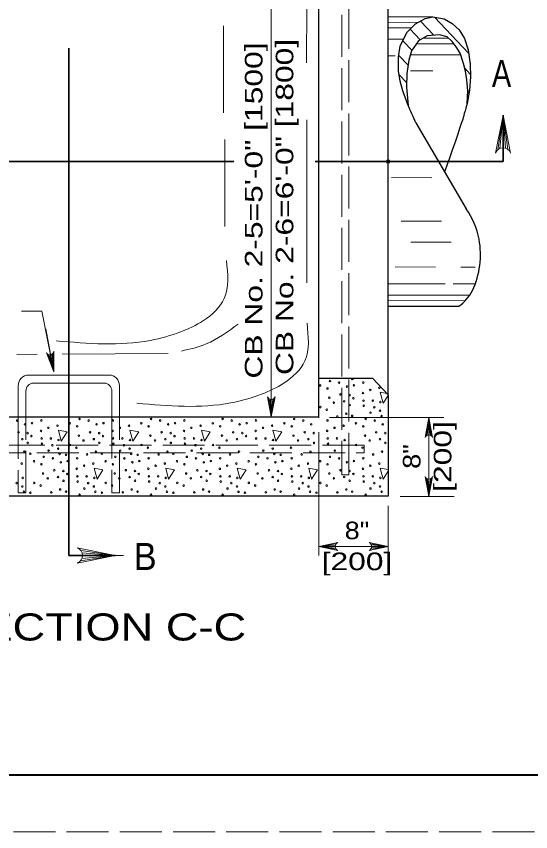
# Model space of a CAD drawing. Extents: x 1329.9 to 1363.9, y 715.5 to 737.5.
# Drawn here: x 1350.19 to 1354.75, y 715.5 to 722.72 of the extents above; entities that cross this region are included whole.
import ezdxf
from ezdxf.enums import TextEntityAlignment as Align

# ---------------------------------------------------------------- set-up
doc = ezdxf.new("R2010")
doc.units = 0
doc.header["$LTSCALE"] = 0.062
doc.header["$PDMODE"] = 32
doc.header["$PDSIZE"] = 0.031
doc.linetypes.add('DASH_DOUBLE_DOT', pattern=[9.2, 5, -1.2, 0.3, -1.2, 0.3, -1.2])
doc.linetypes.add('LONG_DASHED', pattern=[7.5, 6, -1.5])
doc.layers.add('1', color=7, linetype='Continuous', lineweight=13)

msp = doc.modelspace()

# ---------------------------------------------------------------- linework, layer by layer
at = {"layer": '1'}
for p, q in [((1352.44608, 719.17433), (1352.44608, 723.75258)), ((1352.75967, 722.31133), (1352.76208, 722.82492)), ((1353.48483, 722.72117), (1353.88033, 722.72058)), ((1353.89325, 722.71792), (1354.19717, 722.39533)), ((1352.02267, 721.87), (1352.02133, 722.64067)), ((1353.48467, 722.6715), (1353.74925, 722.671)), ((1353.76842, 722.68158), (1353.88667, 722.556)), ((1353.48467, 722.62183), (1353.68817, 722.6215)), ((1353.67675, 722.61), (1353.76625, 722.515)), ((1353.48458, 722.52233), (1353.61992, 722.52217)), ((1353.6135, 722.50825), (1353.6925, 722.42433)), ((1353.795, 722.53158), (1354.01642, 722.53125)), ((1353.73333, 722.48192), (1354.06483, 722.48133)), ((1353.48425, 722.37333), (1353.5445, 722.37308)), ((1353.57692, 722.37808), (1353.65975, 722.29008)), ((1353.67925, 722.38258), (1354.12558, 722.38192)), ((1353.5805, 722.2055), (1353.64717, 722.13458)), ((1353.68183, 722.24175), (1353.87867, 722.24142)), ((1354.162, 722.26358), (1354.21125, 722.21142)), ((1354.18892, 722.06625), (1354.2015, 722.05308)), ((1354.18908, 722.06125), (1354.20067, 722.04875)), ((1354.18533, 721.99475), (1354.18992, 721.99)), ((1353.65158, 721.96108), (1353.65992, 721.952)), ((1353.65917, 721.93992), (1353.66133, 721.93775)), ((1354.45492, 721.54117), (1354.502, 721.84933)), ((1354.47467, 721.55283), (1354.502, 721.84933)), ((1354.502, 721.55817), (1354.502, 721.84933)), ((1354.52358, 721.555), (1354.502, 721.84933)), ((1354.54467, 721.54475), (1354.502, 721.84933)), ((1352.76317, 720.36333), (1352.76058, 721.80692)), ((1352.03592, 720.86092), (1352.03458, 721.63167)), ((1353.51117, 721.29467), (1353.86883, 721.29425)), ((1353.59808, 720.90783), (1353.95575, 720.90742)), ((1353.68517, 720.72367), (1354.04283, 720.72317)), ((1353.54592, 720.50267), (1353.90358, 720.50217)), ((1354.12883, 720.50183), (1354.25567, 720.50175)), ((1353.4815, 720.35375), (1353.9885, 720.35292)), ((1354.0585, 720.35292), (1354.25542, 720.35258)), ((1353.48125, 720.25433), (1354.20592, 720.25317)), ((1353.48125, 720.20467), (1354.16575, 720.2035)), ((1350.23242, 720.11083), (1350.41208, 720.11083)), ((1350.51892, 719.57433), (1350.41208, 720.11083)), ((1350.44733, 719.95367), (1350.51892, 719.57433)), ((1350.18917, 719.72842), (1350.37, 719.72883)), ((1350.46817, 719.72808), (1350.51892, 719.57433)), ((1350.4795, 719.72492), (1350.51892, 719.57433)), ((1350.49033, 719.72542), (1350.51892, 719.57433)), ((1350.50333, 719.73108), (1350.51892, 719.57433)), ((1350.51183, 719.73925), (1350.51892, 719.57433)), ((1350.59333, 719.72933), (1351.53267, 719.73492)), ((1351.01, 719.54458), (1350.29225, 719.54458)), ((1350.33708, 719.47333), (1350.96517, 719.47333)), ((1350.2025, 719.44958), (1350.2025, 719.17383)), ((1350.26983, 719.17208), (1350.26983, 719.40208)), ((1351.03242, 719.40208), (1351.03242, 719.17608)), ((1351.09967, 719.17383), (1351.09967, 719.44958)), ((1353.4725, 719.38092), (1353.41317, 719.39242)), ((1352.42475, 719.3355), (1352.44608, 719.17433)), ((1352.43533, 719.33008), (1352.44608, 719.17433)), ((1352.46958, 719.33742), (1352.44608, 719.17433)), ((1352.45975, 719.33125), (1352.44608, 719.17433)), ((1352.44608, 719.32842), (1352.44608, 719.17433)), ((1352.86742, 719.17433), (1352.86742, 719.1655)), ((1353.97692, 719.16825), (1352.96392, 719.16825)), ((1353.82008, 719.00517), (1353.84367, 719.16825)), ((1353.83, 719.01133), (1353.84367, 719.16825)), ((1353.84367, 718.46808), (1353.84367, 719.16825)), ((1353.84367, 719.01417), (1353.84367, 719.16825)), ((1353.85442, 719.0125), (1353.84367, 719.16825)), ((1353.865, 719.00708), (1353.84367, 719.16825)), ((1352.86742, 719.03958), (1352.86742, 717.9465)), ((1353.48292, 718.70717), (1353.41317, 718.72083)), ((1353.41317, 718.72083), (1353.43875, 718.6235)), ((1353.43875, 718.6235), (1353.48292, 718.693)), ((1353.82233, 718.62933), (1353.84367, 718.46808)), ((1353.83292, 718.62383), (1353.84367, 718.46808)), ((1353.86717, 718.63125), (1353.84367, 718.46808)), ((1353.85733, 718.62508), (1353.84367, 718.46808)), ((1353.84367, 718.62217), (1353.84367, 718.46808)), ((1353.58833, 718.46808), (1354.0685, 718.46808)), ((1353.48158, 718.38683), (1353.48158, 717.9465)), ((1353.01975, 718.04775), (1352.86742, 718.02517)), ((1353.01458, 718.03658), (1352.86742, 718.02517)), ((1352.86742, 718.02517), (1353.48158, 718.02517)), ((1353.013, 718.02517), (1352.86742, 718.02517)), ((1353.01567, 718.01075), (1352.86742, 718.02517)), ((1353.0215, 718.00025), (1352.86742, 718.02517)), ((1353.3275, 718.05017), (1353.48158, 718.02517)), ((1353.32925, 718.00267), (1353.48158, 718.02517)), ((1353.33333, 718.03967), (1353.48158, 718.02517)), ((1353.33442, 718.01383), (1353.48158, 718.02517)), ((1353.336, 718.02517), (1353.48158, 718.02517)), ((1350.75433, 717.89917), (1351.06258, 717.94633)), ((1350.75792, 717.98892), (1351.06258, 717.94633)), ((1350.766, 717.91892), (1351.06258, 717.94633)), ((1350.76825, 717.96783), (1351.06258, 717.94633)), ((1350.77142, 717.94633), (1351.06258, 717.94633))]:
    msp.add_line(p, q, dxfattribs=at)
at = {"layer": '1', "lineweight": 25}
for p, q in [((1353.483, 719.36825), (1353.483, 723.55683)), ((1352.86742, 719.51625), (1352.86742, 723.41067)), ((1353.7295, 721.781), (1354.174, 721.01808)), ((1353.48108, 720.15492), (1354.10975, 720.154))]:
    msp.add_line(p, q, dxfattribs=at)
at = {"layer": '1', "lineweight": 35}
for p, q in [((1350.65133, 717.94633), (1350.65133, 722.44125)), ((1354.502, 721.84933), (1354.502, 721.43808)), ((1347.83075, 721.43808), (1352.11375, 721.43808)), ((1352.83567, 721.43808), (1354.502, 721.43808)), ((1351.06258, 717.94633), (1350.65133, 717.94633))]:
    msp.add_line(p, q, dxfattribs=at)
at = {"layer": '1', "linetype": 'LONG_DASHED'}
for p, q in [((1350.2025, 719.17383), (1350.2025, 718.49975)), ((1350.26983, 718.49975), (1350.26983, 719.17208)), ((1351.03242, 719.17608), (1351.03242, 718.49975)), ((1351.09967, 718.49975), (1351.09967, 719.17383)), ((1350.2025, 718.49975), (1350.26983, 718.49975)), ((1351.03242, 718.49975), (1351.09967, 718.49975))]:
    msp.add_line(p, q, dxfattribs=at)
at = {"layer": '1', "linetype": 'DASH_DOUBLE_DOT'}
msp.add_line((1351.13717, 717.94633), (1350.65133, 717.94633), dxfattribs=at)
at = {"layer": '1', "linetype": 'LONG_DASHED'}
for points in [[(1329.86333, 715.4975), (1363.86333, 715.4975), (1363.86333, 737.4975), (1329.86333, 737.4975)], [(1353.13433, 724.15242), (1353.07167, 724.15242), (1353.07167, 718.66), (1353.13433, 718.66)], [(1348.00833, 718.85575), (1353.27142, 718.85575), (1353.27142, 718.92208), (1348.00833, 718.92208)]]:
    msp.add_lwpolyline(points, close=True, dxfattribs=at)
at = {"layer": '1', "lineweight": 25}
for points in [[(1363.36333, 715.9975), (1331.86333, 715.9975), (1331.86333, 736.9975)], [(1353.66167, 721.933), (1353.6135, 722.06458), (1353.58942, 722.1505), (1353.57417, 722.24242), (1353.57483, 722.36567), (1353.59067, 722.45942), (1353.64733, 722.58125), (1353.7245, 722.65725), (1353.81025, 722.705), (1353.88033, 722.72058), (1353.98033, 722.70117), (1354.04933, 722.66058), (1354.11317, 722.60492), (1354.16142, 722.527), (1354.19308, 722.42867), (1354.20892, 722.30125), (1354.21208, 722.18692), (1354.2045, 722.06992), (1354.18292, 721.95225)], [(1353.66167, 721.933), (1353.6135, 722.06458), (1353.58942, 722.1505), (1353.57417, 722.24242), (1353.57483, 722.36567), (1353.59067, 722.45942), (1353.64733, 722.58125), (1353.7245, 722.65725), (1353.81025, 722.705), (1353.88033, 722.72058), (1353.98033, 722.70117), (1354.04933, 722.66058), (1354.11317, 722.60492), (1354.16142, 722.527), (1354.19308, 722.42867), (1354.20892, 722.30125), (1354.21208, 722.18692), (1354.2045, 722.06992), (1354.18292, 721.95225)], [(1354.18292, 721.95225), (1354.18917, 722.06317), (1354.18017, 722.16175), (1354.16917, 722.23717), (1354.151, 722.305), (1354.12017, 722.39783), (1354.08542, 722.454), (1354.04917, 722.5025), (1354.00517, 722.54117), (1353.93942, 722.56067), (1353.82992, 722.55117), (1353.75117, 722.50667), (1353.68908, 722.41983), (1353.66692, 722.33667), (1353.64858, 722.21875), (1353.6465, 722.09683), (1353.66167, 721.933)], [(1354.18292, 721.95225), (1354.18917, 722.06317), (1354.18017, 722.16175), (1354.16917, 722.23717), (1354.151, 722.305), (1354.12017, 722.39783), (1354.08542, 722.454), (1354.04917, 722.5025), (1354.00517, 722.54117), (1353.93942, 722.56067), (1353.82992, 722.55117), (1353.75117, 722.50667), (1353.68908, 722.41983), (1353.66692, 722.33667), (1353.64858, 722.21875), (1353.6465, 722.09683), (1353.66167, 721.933)], [(1348.49467, 719.17433), (1352.86742, 719.17433), (1352.86742, 719.51625), (1353.34492, 719.51625), (1353.483, 719.37008)], [(1353.483, 719.36825), (1353.483, 718.47142), (1347.83075, 718.47142), (1347.83075, 719.34)]]:
    msp.add_lwpolyline(points, dxfattribs=at)
at = {"layer": '1', "lineweight": 40}
msp.add_lwpolyline([(1331.86333, 736.9975), (1363.36333, 736.9975), (1363.36333, 715.9975), (1331.86333, 715.9975)], close=True, dxfattribs=at)
msp.add_lwpolyline([(1331.86333, 736.9975), (1363.36333, 736.9975), (1363.36333, 715.9975), (1331.86333, 715.9975)], close=True, dxfattribs=at)
at = {"layer": '1'}
for points in [[(1354.43475, 721.51283), (1354.502, 721.84933), (1354.56933, 721.51283)], [(1350.51892, 719.756), (1350.51892, 719.57433), (1350.453, 719.742)], [(1353.41317, 719.39242), (1353.43875, 719.29508), (1353.48292, 719.36467)], [(1352.47975, 719.35242), (1352.44608, 719.17433), (1352.41242, 719.35242)], [(1353.81, 718.99017), (1353.84367, 719.16825), (1353.87733, 718.99017)], [(1353.87733, 718.64617), (1353.84367, 718.46808), (1353.81, 718.64617)], [(1350.72608, 717.879), (1351.06258, 717.94633), (1350.72608, 718.01358)], [(1353.03567, 717.98958), (1352.86742, 718.02517), (1353.03567, 718.06083)], [(1353.31333, 718.06083), (1353.48158, 718.02517), (1353.31333, 717.98958)]]:
    msp.add_lwpolyline(points, dxfattribs=at)
for points in [[(1350.55833, 719.05658), (1350.584, 718.95933), (1350.63625, 719.0415)], [(1351.19275, 719.05658), (1351.21833, 718.95933), (1351.27058, 719.0415)], [(1351.82717, 719.05658), (1351.85283, 718.95933), (1351.905, 719.0415)], [(1352.4615, 719.05658), (1352.48717, 718.95933), (1352.53942, 719.0415)], [(1350.87558, 718.72083), (1350.90117, 718.6235), (1350.95342, 718.70567)], [(1351.50992, 718.72083), (1351.53558, 718.6235), (1351.58783, 718.70567)], [(1352.14433, 718.72083), (1352.16992, 718.6235), (1352.22225, 718.70567)], [(1352.77875, 718.72083), (1352.80442, 718.6235), (1352.85658, 718.70567)]]:
    msp.add_lwpolyline(points, close=True, dxfattribs=at)
for centre, start, end in [((1354.50209, 721.4857), 22.08782, 157.91395), ((1350.69893, 717.94637), 292.08605, 67.91218)]:
    msp.add_arc(centre, 0.07261, start, end, dxfattribs=at)
at = {"layer": '1', "lineweight": 25}
for centre, major_axis, start_param, end_param in [((1353.69011, 720.62359), (0, 0.64669), 4.9058986, 5.3686347), ((1353.62561, 720.61253), (0, 0.71577), 4.251341, 4.9027182), ((1353.8771, 720.50864), (0, -0.43184), 0.6070417, 1.0508543)]:
    msp.add_ellipse(centre, major_axis=major_axis, ratio=0.944544, start_param=start_param, end_param=end_param, dxfattribs=at)
at = {"layer": '1'}
for centre, major_axis, start_param, end_param in [((1350.48328, 719.76316), (0, -0.03844), 5.2952095, 7.6658226), ((1350.29224, 719.4496), (0, 0.09498), 6.2831853, 7.8539816), ((1351.00998, 719.4496), (0, 0.09498), 4.712389, 6.2831853), ((1350.3371, 719.4021), (0, 0.07124), 6.2831853, 7.8539816), ((1350.96513, 719.4021), (0, 0.07124), 4.712389, 6.2831853), ((1352.44606, 719.36685), (0, -0.03844), 5.0978942, 7.4685073), ((1353.84366, 718.97573), (0, 0.03844), 5.0978942, 7.4685073), ((1353.84365, 718.66064), (0, -0.03844), 5.0978942, 7.4685073), ((1353.04931, 718.0252), (0, 0.03844), 0.3855052, 2.7561184), ((1353.29968, 718.0252), (0, -0.03844), 0.3855052, 2.7561184)]:
    msp.add_ellipse(centre, major_axis=major_axis, ratio=0.944544, start_param=start_param, end_param=end_param, dxfattribs=at)
for centre in [(1352.87983, 719.45284), (1352.96637, 719.49185), (1353.04715, 719.47764), (1353.16451, 719.50932), (1353.17905, 719.45407), (1353.26216, 719.47848), (1352.94496, 719.42564), (1353.05973, 719.37308), (1353.11736, 719.44316), (1353.25904, 719.38573), (1353.32406, 719.41293), (1353.40548, 719.43196), (1352.9604, 719.34403), (1353.09314, 719.3123), (1353.14056, 719.36609), (1353.17424, 719.3395), (1353.26417, 719.31862), (1353.34643, 719.31862), (1353.41404, 719.30502), (1352.88157, 719.26058), (1352.93809, 719.23702), (1353.00153, 719.30049), (1353.14141, 719.27933), (1353.2667, 719.27239), (1353.36012, 719.25879), (1353.41061, 719.22885), (1353.03261, 719.17691), (1353.11144, 719.20226), (1353.16367, 719.18323), (1353.32666, 719.21071), (1353.42435, 719.18172), (1350.19236, 719.14181), (1350.26256, 719.10734), (1350.32426, 719.11825), (1350.40736, 719.14265), (1350.55068, 719.09614), (1350.65943, 719.11702), (1350.72456, 719.08982), (1350.74597, 719.15603), (1350.82675, 719.14181), (1350.89696, 719.10734), (1350.95866, 719.11825), (1351.04176, 719.14265), (1351.18508, 719.09614), (1351.29383, 719.11702), (1351.35896, 719.08982), (1351.38037, 719.15603), (1351.46115, 719.14181), (1351.53136, 719.10734), (1351.59305, 719.11825), (1351.67616, 719.14265), (1351.81948, 719.09614), (1351.92823, 719.11702), (1351.99336, 719.08982), (1352.01477, 719.15603), (1352.09555, 719.14181), (1352.16576, 719.10734), (1352.22745, 719.11825), (1352.31056, 719.14265), (1352.45388, 719.09614), (1352.56263, 719.11702), (1352.62776, 719.08982), (1352.64917, 719.15603), (1352.72995, 719.14181), (1352.80016, 719.10734), (1352.94496, 719.14265), (1353.08828, 719.09614), (1353.19703, 719.11702), (1353.26216, 719.08982), (1353.28357, 719.15603), (1353.36435, 719.14181), (1353.43456, 719.10734), (1350.20494, 719.03726), (1350.28577, 719.03026), (1350.40424, 719.04991), (1350.46927, 719.07711), (1350.83934, 719.03726), (1350.92017, 719.03026), (1351.03864, 719.04991), (1351.10367, 719.07711), (1351.47374, 719.03726), (1351.55457, 719.03026), (1351.67304, 719.04991), (1351.73807, 719.07711), (1352.10813, 719.03726), (1352.18897, 719.03026), (1352.30744, 719.04991), (1352.37247, 719.07711), (1352.74253, 719.03726), (1352.82337, 719.03026), (1352.94184, 719.04991), (1353.00687, 719.07711), (1353.37693, 719.03726), (1353.45776, 719.03026), (1350.23835, 718.97648), (1350.28662, 718.94351), (1350.31945, 719.00368), (1350.40937, 718.9828), (1350.49163, 718.9828), (1350.55925, 718.9692), (1350.74, 719.00821), (1350.78113, 718.96467), (1350.87275, 718.97648), (1350.92102, 718.94351), (1350.95385, 719.00368), (1351.04377, 718.9828), (1351.12603, 718.9828), (1351.19365, 718.9692), (1351.3744, 719.00821), (1351.41553, 718.96467), (1351.50715, 718.97648), (1351.55541, 718.94351), (1351.58824, 719.00368), (1351.67817, 718.9828), (1351.76043, 718.9828), (1351.82805, 718.9692), (1352.0088, 719.00821), (1352.04993, 718.96467), (1352.14155, 718.97648), (1352.22264, 719.00368), (1352.31257, 718.9828), (1352.39483, 718.9828), (1352.46245, 718.9692), (1352.6432, 719.00821), (1352.68433, 718.96467), (1352.77594, 718.97648), (1352.82421, 718.94351), (1352.94697, 718.9828), (1353.02923, 718.9828), (1353.09684, 718.9692), (1353.27759, 719.00821), (1353.31873, 718.96467), (1353.41034, 718.97648), (1353.45861, 718.94351), (1350.41191, 718.93657), (1350.47186, 718.87489), (1350.50533, 718.92297), (1350.55581, 718.89302), (1350.66118, 718.92476), (1350.71769, 718.9012), (1351.04631, 718.93657), (1351.10626, 718.87489), (1351.13972, 718.92297), (1351.19021, 718.89302), (1351.29557, 718.92476), (1351.35209, 718.9012), (1351.68071, 718.93657), (1351.74066, 718.87489), (1351.77412, 718.92297), (1351.82461, 718.89302), (1351.92997, 718.92476), (1351.98649, 718.9012), (1352.37506, 718.87489), (1352.45901, 718.89302), (1352.62089, 718.9012), (1352.94951, 718.93657), (1353.00946, 718.87489), (1353.19877, 718.92476), (1353.25529, 718.9012), (1350.25664, 718.86644), (1350.30887, 718.84741), (1350.42877, 718.82021), (1350.50955, 718.80599), (1350.56956, 718.8459), (1350.62692, 718.83767), (1350.72456, 718.80683), (1350.81222, 718.84108), (1350.89104, 718.86644), (1350.94327, 718.84741), (1351.06317, 718.82021), (1351.14395, 718.80599), (1351.20396, 718.8459), (1351.26132, 718.83767), (1351.35896, 718.80683), (1351.44661, 718.84108), (1351.52544, 718.86644), (1351.57767, 718.84741), (1351.69757, 718.82021), (1351.77835, 718.80599), (1351.83836, 718.8459), (1351.89572, 718.83767), (1351.99336, 718.80683), (1352.08101, 718.84108), (1352.15984, 718.86644), (1352.33197, 718.82021), (1352.41275, 718.80599), (1352.47275, 718.8459), (1352.53011, 718.83767), (1352.62776, 718.80683), (1352.71541, 718.84108), (1352.79424, 718.86644), (1352.96637, 718.82021), (1353.04715, 718.80599), (1353.26216, 718.80683), (1353.34981, 718.84108), (1353.42863, 718.86644), (1350.23349, 718.76032), (1350.34223, 718.7812), (1350.40736, 718.75399), (1350.57976, 718.77151), (1350.64146, 718.78243), (1350.78647, 718.74129), (1350.86788, 718.76032), (1350.97663, 718.7812), (1351.04176, 718.75399), (1351.21416, 718.77151), (1351.27586, 718.78243), (1351.42087, 718.74129), (1351.50228, 718.76032), (1351.61103, 718.7812), (1351.67616, 718.75399), (1351.84856, 718.77151), (1351.91025, 718.78243), (1352.05527, 718.74129), (1352.13668, 718.76032), (1352.24543, 718.7812), (1352.31056, 718.75399), (1352.48296, 718.77151), (1352.54465, 718.78243), (1352.68967, 718.74129), (1352.77108, 718.76032), (1352.87983, 718.7812), (1352.94496, 718.75399), (1353.11736, 718.77151), (1353.17905, 718.78243), (1353.32406, 718.74129), (1353.40548, 718.76032), (1350.4228, 718.67239), (1350.52214, 718.70144), (1350.60297, 718.69444), (1350.63665, 718.66786), (1350.72144, 718.71409), (1351.0572, 718.67239), (1351.15654, 718.70144), (1351.23737, 718.69444), (1351.27104, 718.66786), (1351.35584, 718.71409), (1351.6916, 718.67239), (1351.79093, 718.70144), (1351.87177, 718.69444), (1351.90544, 718.66786), (1351.99024, 718.71409), (1352.326, 718.67239), (1352.42533, 718.70144), (1352.50617, 718.69444), (1352.53984, 718.66786), (1352.62464, 718.71409), (1352.9604, 718.67239), (1353.05973, 718.70144), (1353.14056, 718.69444), (1353.17424, 718.66786), (1353.25904, 718.71409), (1350.18813, 718.58715), (1350.24205, 718.63338), (1350.34398, 718.58894), (1350.46393, 718.62884), (1350.55555, 718.64065), (1350.60382, 718.60769), (1350.72657, 718.64698), (1350.72911, 718.60075), (1350.80883, 718.64698), (1350.82252, 718.58715), (1350.87645, 718.63338), (1350.97838, 718.58894), (1351.09833, 718.62884), (1351.18995, 718.64065), (1351.23821, 718.60769), (1351.36097, 718.64698), (1351.36351, 718.60075), (1351.44323, 718.64698), (1351.45692, 718.58715), (1351.51085, 718.63338), (1351.61277, 718.58894), (1351.73273, 718.62884), (1351.82435, 718.64065), (1351.87261, 718.60769), (1351.99537, 718.64698), (1351.99791, 718.60075), (1352.07763, 718.64698), (1352.09132, 718.58715), (1352.14525, 718.63338), (1352.24717, 718.58894), (1352.36713, 718.62884), (1352.45874, 718.64065), (1352.50701, 718.60769), (1352.62977, 718.64698), (1352.63231, 718.60075), (1352.71203, 718.64698), (1352.72572, 718.58715), (1352.77964, 718.63338), (1352.88157, 718.58894), (1353.00153, 718.62884), (1353.09314, 718.64065), (1353.14141, 718.60769), (1353.26417, 718.64698), (1353.2667, 718.60075), (1353.34643, 718.64698), (1353.36012, 718.58715), (1353.41404, 718.63338), (1350.23861, 718.5572), (1350.25236, 718.51007), (1350.40049, 718.56537), (1350.57384, 718.53062), (1350.62607, 718.51159), (1350.78906, 718.53907), (1350.87301, 718.5572), (1350.88676, 718.51007), (1351.03489, 718.56537), (1351.20824, 718.53062), (1351.26047, 718.51159), (1351.42346, 718.53907), (1351.50741, 718.5572), (1351.52116, 718.51007), (1351.66929, 718.56537), (1351.84264, 718.53062), (1351.89487, 718.51159), (1352.05786, 718.53907), (1352.14181, 718.5572), (1352.15556, 718.51007), (1352.30369, 718.56537), (1352.47704, 718.53062), (1352.52927, 718.51159), (1352.69226, 718.53907), (1352.77621, 718.5572), (1352.78995, 718.51007), (1352.93809, 718.56537), (1353.11144, 718.53062), (1353.16367, 718.51159), (1353.32666, 718.53907), (1353.41061, 718.5572), (1353.42435, 718.51007), (1350.30972, 718.50185), (1350.49502, 718.50526), (1350.74597, 718.48438), (1350.94412, 718.50185), (1351.12942, 718.50526), (1351.38037, 718.48438), (1351.57852, 718.50185), (1351.76381, 718.50526), (1352.01477, 718.48438), (1352.21292, 718.50185), (1352.39821, 718.50526), (1352.64917, 718.48438), (1352.84731, 718.50185), (1353.03261, 718.50526), (1353.28357, 718.48438)]:
    msp.add_ellipse(centre, major_axis=(0, 0.00718), ratio=0.944544, dxfattribs=at)
at = {"layer": '1', "lineweight": 25}
for points in [[(1353.7295, 721.781), (1353.70283, 721.83708), (1353.6805, 721.88758), (1353.66167, 721.933)], [(1354.18292, 721.95225), (1354.15775, 721.84975), (1354.10483, 721.68525), (1353.9855, 721.351)]]:
    msp.add_open_spline(points, degree=3, dxfattribs=at)
at = {"layer": '1'}
for points in [[(1350.53983, 719.84792), (1351.37392, 719.85192), (1351.64525, 719.929), (1351.84383, 720.02708), (1352.02908, 720.22333), (1352.04858, 720.55958)], [(1351.25458, 719.29442), (1352.08867, 719.29842), (1352.36, 719.3755), (1352.55858, 719.47358), (1352.74383, 719.66983), (1352.76333, 720.00608)], [(1351.64983, 719.75775), (1351.86958, 719.82017), (1352.15167, 719.99692)]]:
    msp.add_spline(points, degree=3, dxfattribs=at)
msp.add_point((1353.483, 721.43808), dxfattribs=at)

# ---------------------------------------------------------------- texts
at = {"layer": '1', "width": 1.35}
for s, p in [('CB No. 2-6=6\'-0" [1800]', (1352.64183, 719.54492)), ('CB No. 2-5=5\'-0" [1500]', (1352.36833, 719.51358))]:
    msp.add_text(s, height=0.156, rotation=90, dxfattribs=at).set_placement(p)
at = {"layer": '1'}
for s, height, width, p in [('A', 0.24, 0.8, (1354.48867, 722.09817)), ('8"', 0.156, 1.15, (1353.2065, 718.08958)), ('B', 0.24, 0.95, (1351.32825, 717.817)), ('[200]', 0.156, 1.35, (1353.2065, 717.8155))]:
    msp.add_text(s, height=height, dxfattribs=dict(at, width=width)).set_placement(p, align=Align.CENTER)
for s, width, p in [('[200]', 1.35, (1354.0435, 718.82283)), ('8"', 1.15, (1353.76942, 718.82283))]:
    msp.add_text(s, height=0.156, rotation=90, dxfattribs=dict(at, width=width)).set_placement(p, align=Align.CENTER)
at = {"layer": '1', "width": 1.25}
msp.add_text('SECTION C-C', height=0.24, dxfattribs=at).set_placement((1349.61633, 717.192))

doc.saveas('drawing.dxf')
